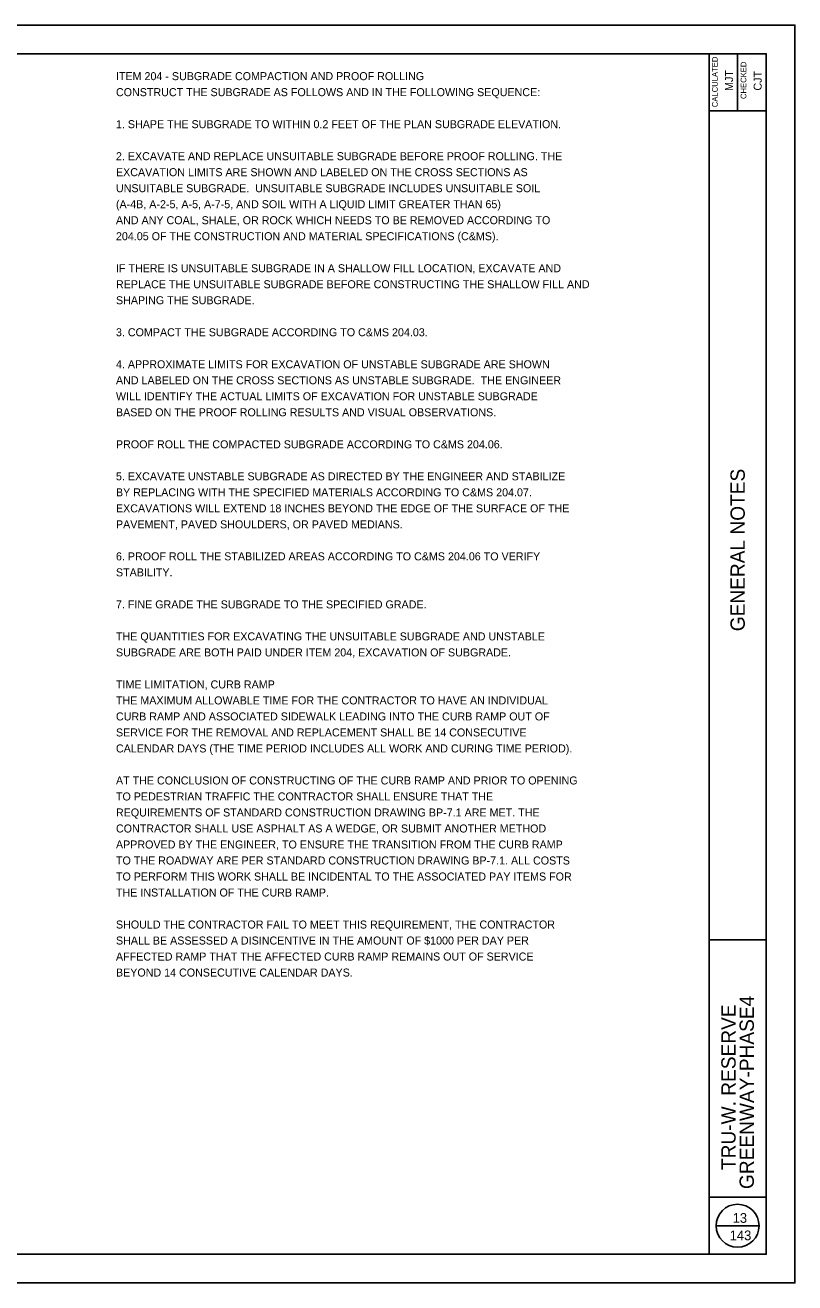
# Model space of a CAD drawing. Extents: x -16 to 195, y -13 to 9.
# Drawn here: x 181.1 to 194.56, y -12.91 to 9.09 of the extents above; entities that cross this region are included whole.
import ezdxf

# ---------------------------------------------------------------- set-up
doc = ezdxf.new("R2010")
doc.units = 0
for name, color, linetype in [('SH_Border', 7, 'Continuous'), ('SH_Cut_Line', 7, 'Continuous'), ('SH_Data', 7, 'Continuous'), ('SH_Text', 7, 'Continuous'), ('TX_P_1', 7, 'Continuous')]:
    doc.layers.add(name, color=color, linetype=linetype)

msp = doc.modelspace()

# ---------------------------------------------------------------- linework, layer by layer
at = {"layer": 'SH_Border'}
for p, q in [((193.059, -12.407), (193.059, 8.593)), ((193.559, 8.593), (193.559, 7.593)), ((193.059, 7.593), (194.059, 7.593)), ((193.059, -6.907), (194.059, -6.907)), ((193.059, -11.407), (194.059, -11.407))]:
    msp.add_line(p, q, dxfattribs=at)
msp.add_lwpolyline([(162.559, 8.593), (194.059, 8.593), (194.059, -12.407), (162.559, -12.407)], close=True, dxfattribs=at)
at = {"layer": 'SH_Cut_Line'}
msp.add_lwpolyline([(160.559, -12.907), (194.559, -12.907), (194.559, 9.093), (160.559, 9.093)], close=True, dxfattribs=at)
at = {"layer": 'SH_Data'}
msp.add_line((193.184, -11.907), (193.934, -11.907), dxfattribs=at)
msp.add_circle((193.559, -11.907), 0.375, dxfattribs=at)

# ---------------------------------------------------------------- texts
for s, height, p in [('CALCULATED', 0.1, (193.211, 7.658)), ('CHECKED', 0.1, (193.711, 7.801)), ('MJT', 0.14, (193.479, 7.942)), ('CJT', 0.14, (193.979, 7.949)), ('GENERAL NOTES', 0.25, (193.684, -1.509)), ('GREENWAY-PHASE4', 0.25, (193.843, -11.266)), ('TRU-W. RESERVE', 0.25, (193.524, -10.934))]:
    msp.add_text(s, height=height, rotation=90, dxfattribs=at).set_placement(p)
for s, p in [('13', (193.471, -11.857)), ('143', (193.419, -12.162))]:
    msp.add_text(s, height=0.17, dxfattribs=at).set_placement(p)
at = {"layer": 'SH_Text'}
for s, p in [('CONSTRUCT THE SUBGRADE AS FOLLOWS AND IN THE FOLLOWING SEQUENCE:', (182.69, 7.851)), ('1. SHAPE THE SUBGRADE TO WITHIN 0.2 FEET OF THE PLAN SUBGRADE ELEVATION.', (182.69, 7.291)), ('2. EXCAVATE AND REPLACE UNSUITABLE SUBGRADE BEFORE PROOF ROLLING. THE', (182.69, 6.731)), ('EXCAVATION LIMITS ARE SHOWN AND LABELED ON THE CROSS SECTIONS AS', (182.69, 6.451)), ('UNSUITABLE SUBGRADE.  UNSUITABLE SUBGRADE INCLUDES UNSUITABLE SOIL', (182.69, 6.171)), ('(A-4B, A-2-5, A-5, A-7-5, AND SOIL WITH A LIQUID LIMIT GREATER THAN 65)', (182.69, 5.891)), ('AND ANY COAL, SHALE, OR ROCK WHICH NEEDS TO BE REMOVED ACCORDING TO', (182.69, 5.611)), ('204.05 OF THE CONSTRUCTION AND MATERIAL SPECIFICATIONS (C&MS).', (182.69, 5.331)), ('IF THERE IS UNSUITABLE SUBGRADE IN A SHALLOW FILL LOCATION, EXCAVATE AND', (182.69, 4.771)), ('REPLACE THE UNSUITABLE SUBGRADE BEFORE CONSTRUCTING THE SHALLOW FILL AND', (182.69, 4.491)), ('SHAPING THE SUBGRADE.', (182.69, 4.211)), ('3. COMPACT THE SUBGRADE ACCORDING TO C&MS 204.03.', (182.69, 3.651)), ('4. APPROXIMATE LIMITS FOR EXCAVATION OF UNSTABLE SUBGRADE ARE SHOWN', (182.69, 3.091)), ('AND LABELED ON THE CROSS SECTIONS AS UNSTABLE SUBGRADE.  THE ENGINEER', (182.69, 2.811)), ('WILL IDENTIFY THE ACTUAL LIMITS OF EXCAVATION FOR UNSTABLE SUBGRADE', (182.69, 2.531)), ('BASED ON THE PROOF ROLLING RESULTS AND VISUAL OBSERVATIONS. ', (182.69, 2.251)), ('PROOF ROLL THE COMPACTED SUBGRADE ACCORDING TO C&MS 204.06.', (182.69, 1.691)), ('5. EXCAVATE UNSTABLE SUBGRADE AS DIRECTED BY THE ENGINEER AND STABILIZE', (182.69, 1.131)), ('BY REPLACING WITH THE SPECIFIED MATERIALS ACCORDING TO C&MS 204.07. ', (182.69, 0.851)), ('EXCAVATIONS WILL EXTEND 18 INCHES BEYOND THE EDGE OF THE SURFACE OF THE', (182.69, 0.571)), ('PAVEMENT, PAVED SHOULDERS, OR PAVED MEDIANS.', (182.69, 0.291)), ('6. PROOF ROLL THE STABILIZED AREAS ACCORDING TO C&MS 204.06 TO VERIFY', (182.69, -0.269)), ('STABILITY.', (182.69, -0.549)), ('7. FINE GRADE THE SUBGRADE TO THE SPECIFIED GRADE.', (182.69, -1.109)), ('THE QUANTITIES FOR EXCAVATING THE UNSUITABLE SUBGRADE AND UNSTABLE', (182.69, -1.669)), ('SUBGRADE ARE BOTH PAID UNDER ITEM 204, EXCAVATION OF SUBGRADE.', (182.69, -1.949))]:
    msp.add_text(s, height=0.14, dxfattribs=at).set_placement(p)
at = {"layer": 'TX_P_1'}
for s, p in [('ITEM 204 - SUBGRADE COMPACTION AND PROOF ROLLING', (182.69, 8.131)), ('TIME LIMITATION, CURB RAMP', (182.69, -2.509)), ('THE MAXIMUM ALLOWABLE TIME FOR THE CONTRACTOR TO HAVE AN INDIVIDUAL', (182.69, -2.789)), ('CURB RAMP AND ASSOCIATED SIDEWALK LEADING INTO THE CURB RAMP OUT OF', (182.69, -3.069)), ('SERVICE FOR THE REMOVAL AND REPLACEMENT SHALL BE 14 CONSECUTIVE', (182.69, -3.349)), ('CALENDAR DAYS (THE TIME PERIOD INCLUDES ALL WORK AND CURING TIME PERIOD).', (182.69, -3.629)), ('AT THE CONCLUSION OF CONSTRUCTING OF THE CURB RAMP AND PRIOR TO OPENING', (182.69, -4.189)), ('TO PEDESTRIAN TRAFFIC THE CONTRACTOR SHALL ENSURE THAT THE', (182.69, -4.469)), ('REQUIREMENTS OF STANDARD CONSTRUCTION DRAWING BP-7.1 ARE MET. THE', (182.69, -4.749)), ('CONTRACTOR SHALL USE ASPHALT AS A WEDGE, OR SUBMIT ANOTHER METHOD', (182.69, -5.029)), ('APPROVED BY THE ENGINEER, TO ENSURE THE TRANSITION FROM THE CURB RAMP', (182.69, -5.309)), ('TO THE ROADWAY ARE PER STANDARD CONSTRUCTION DRAWING BP-7.1. ALL COSTS', (182.69, -5.589)), ('TO PERFORM THIS WORK SHALL BE INCIDENTAL TO THE ASSOCIATED PAY ITEMS FOR', (182.69, -5.869)), ('THE INSTALLATION OF THE CURB RAMP.', (182.69, -6.149)), ('SHOULD THE CONTRACTOR FAIL TO MEET THIS REQUIREMENT, THE CONTRACTOR', (182.69, -6.709)), ('SHALL BE ASSESSED A DISINCENTIVE IN THE AMOUNT OF $1000 PER DAY PER', (182.69, -6.989)), ('AFFECTED RAMP THAT THE AFFECTED CURB RAMP REMAINS OUT OF SERVICE', (182.69, -7.269)), ('BEYOND 14 CONSECUTIVE CALENDAR DAYS.', (182.69, -7.549))]:
    msp.add_text(s, height=0.14, dxfattribs=at).set_placement(p)

doc.saveas('drawing.dxf')
